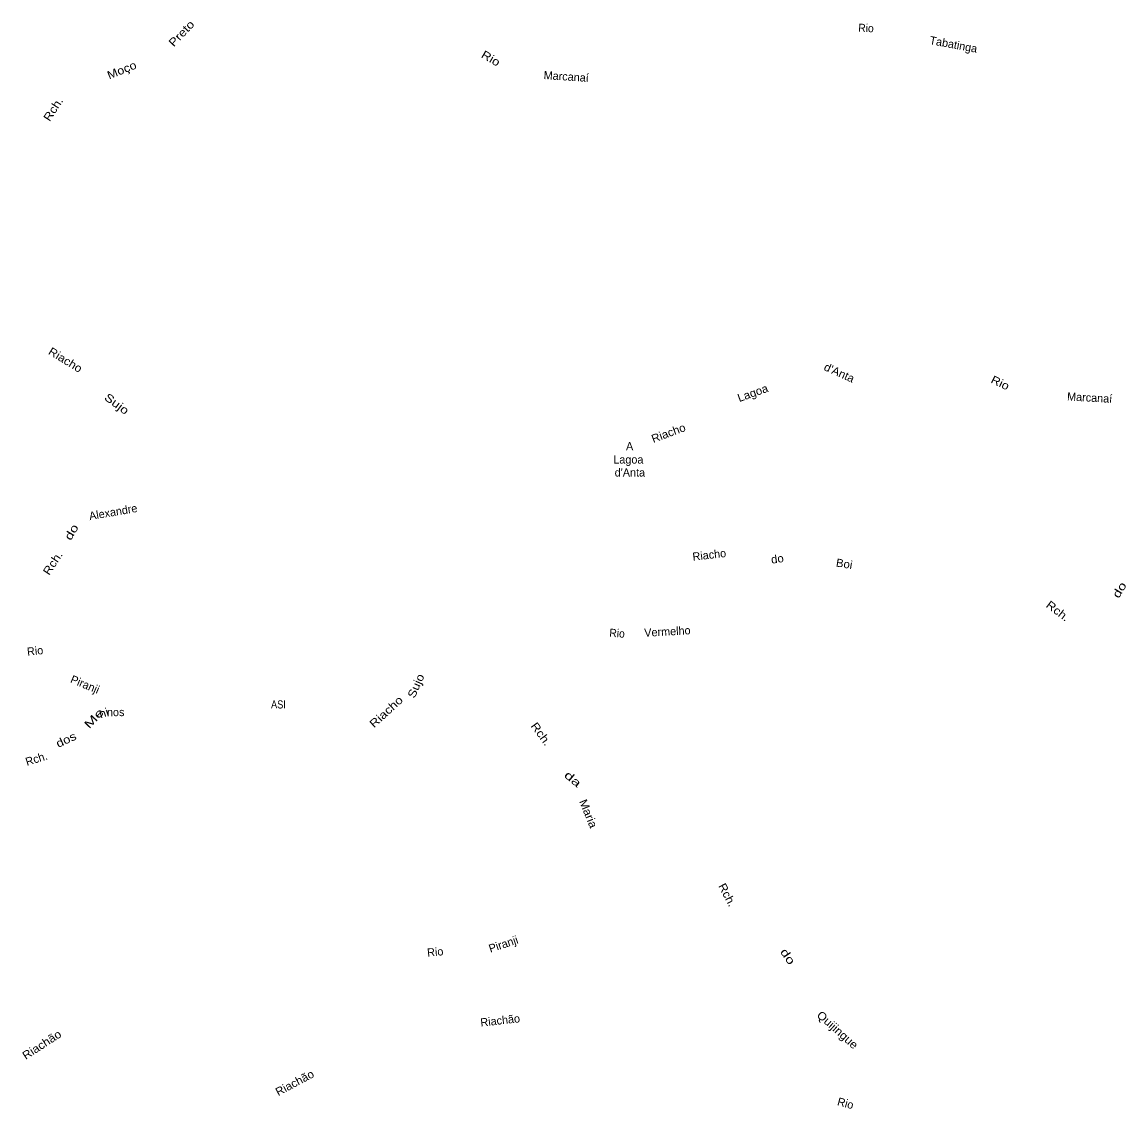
# Model space of a CAD drawing. Extents: x 649844 to 663669, y 8700676 to 8714511.
# Drawn here: x 649869 to 656684, y 8707742 to 8714448 of the extents above; entities that cross this region are included whole.
import ezdxf
from ezdxf.enums import TextEntityAlignment as Align

# ---------------------------------------------------------------- set-up
doc = ezdxf.new("R2010")
doc.units = 0
doc.header["$LTSCALE"] = 20
for name, color, linetype in [('20', 7, 'Continuous'), ('38', 7, 'Continuous'), ('51', 7, 'Continuous')]:
    doc.layers.add(name, color=color, linetype=linetype)

msp = doc.modelspace()

# ---------------------------------------------------------------- texts
at = {"layer": '20'}
msp.add_text('A', height=50, rotation=0.001, dxfattribs=at).set_placement((653619.62, 8711806.45), align=Align.CENTER)
at = {"layer": '38', "width": 0.85}
msp.add_text('ASI', height=50, rotation=0.001, dxfattribs=at).set_placement((651451.64, 8710212.47), align=Align.CENTER)
at = {"layer": '51'}
for s, rotation, width, p in [('Preto', 46.3, 1.2, (650871.01, 8714360.93)), ('Rio', 357.674, 0.95, (655078.05, 8714386.75)), ('Rio', 329.317, 1.2, (652750.17, 8714202.8)), ('Moço', 21.901, 1.15, (650493.87, 8714129.38)), ('Rch.', 56.871, 1.15, (650082.19, 8713897.24)), ('Riacho', 328.455, 1.1, (650123.48, 8712342.3)), ("d'Anta", 335.829, 1.05, (654903.85, 8712262)), ('Rio', 334.349, 1.15, (655896.84, 8712199.54)), ('Lagoa', 19.794, 1.05, (654388.26, 8712136.08)), ('Sujo', 323.129, 1.25, (650438.45, 8712072.27)), ('Riacho', 20.461, 1.05, (653868.03, 8711889.05)), ('do', 59.537, 1.35, (650195.09, 8711288.49)), ('Rch.', 56.574, 1.15, (650079.33, 8711096.56)), ('do', 8.122, 1.05, (654534.87, 8711111.26)), ('Boi', 350.756, 1.05, (654940.78, 8711080.95)), ('do', 58.721, 1.35, (656664.53, 8710931.05)), ('Rch.', 322.765, 1.15, (656248.28, 8710794.23)), ('Rio', 355.79, 0.95, (653540.56, 8710652.17)), ('Sujo', 65.982, 1.15, (652323.18, 8710342.31)), ('Riacho', 42.685, 1.2, (652133.55, 8710173.84)), ('Me', 46.683, 1.5, (650330.97, 8710134.63)), ('ni', 18.933, 1.1, (650381.25, 8710160.95)), ('Rch.', 306.183, 1.15, (653052.99, 8710040.48)), ('dos', 25.287, 1.2, (650151.23, 8709996.96)), ('da', 320.281, 1.5, (653253.05, 8709758.23)), ('Maria', 292.283, 1.1, (653341.7, 8709554.35)), ('Rch.', 297.641, 1.1, (654200.38, 8709050.81)), ('do', 304.188, 1.4, (654575.41, 8708668.28)), ('Quijingue', 318.29, 1.1, (654886.63, 8708210.26)), ('Riachão', 33.022, 1.1, (650004.24, 8708116.97)), ('Riachão', 28.152, 1.05, (651563.72, 8707880.61))]:
    msp.add_text(s, height=50, rotation=rotation, dxfattribs=dict(at, width=width)).set_placement(p, align=Align.CENTER)
for s, rotation, p in [('Tabatinga', 349.45, (655614.41, 8714285.92)), ('Marcanaí', 356.384, (653226.78, 8714087.77)), ('Marcanaí', 356.904, (656458.39, 8712106.11)), ('Alexandre', 9.809, (650435.41, 8711400.21)), ('Riacho', 6.578, (654114.15, 8711135.92)), ('Vermelho', 3.249, (653854.23, 8710662.68)), ('Rio', 6.362, (649952.02, 8710543.21)), ('Piranji', 337.193, (650248.1, 8710338.16)), ('nos', 0.357, (650446.82, 8710165.17)), ('Rch.', 17.515, (649964.86, 8709878.55)), ('Piranji', 18.558, (652848.3, 8708734.77)), ('Rio', 5.224, (652421.65, 8708685.68)), ('Riachão', 6.33, (652823.08, 8708262.95)), ('Rio', 345.129, (654946.24, 8707752.3))]:
    msp.add_text(s, height=50, rotation=rotation, dxfattribs=at).set_placement(p, align=Align.CENTER)
for s, p in [('Lagoa ', (653621.06, 8711723.94)), ("d'Anta", (653621.06, 8711643.94))]:
    msp.add_text(s, height=50, dxfattribs=at).set_placement(p, align=Align.CENTER)

doc.saveas('drawing.dxf')
